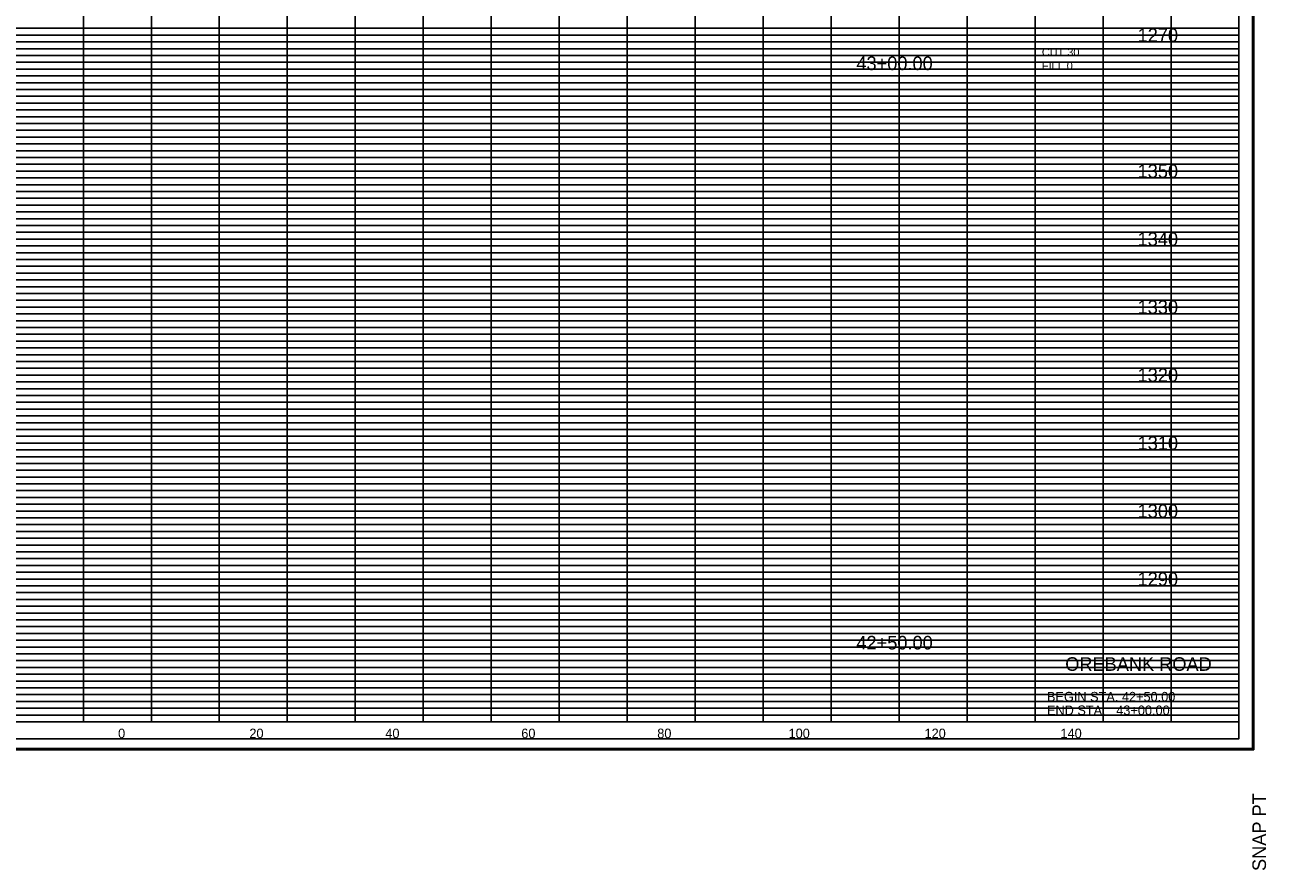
# Model space of a CAD drawing. Extents: x 980 to 1324, y 978 to 2847.
# Drawn here: x 1141.4 to 1324, y 978.2 to 1102.5 of the extents above; entities that cross this region are included whole.
import ezdxf

# ---------------------------------------------------------------- set-up
doc = ezdxf.new("R2010")
doc.units = 0
for name, color, linetype in [('DESIGN - SHEET - Corner Text', 7, 'Continuous'), ('DESIGN - SHEET - Light Grid', 7, 'Continuous'), ('DESIGN - SHEET - Linework', 7, 'Continuous'), ('DESIGN - SHEET - Plot Shape', 7, 'Continuous'), ('DESIGN - TYPICAL - Text', 7, 'Continuous')]:
    doc.layers.add(name, color=color, linetype=linetype)

# ---------------------------------------------------------------- blocks, each defined once
blk = doc.blocks.new('XSTSHT')
at = {"layer": 'DESIGN - SHEET - Light Grid'}
for p, q in [((8, 10.2), (16, 10.2)), ((8, 10.1), (16, 10.1)), ((16, 10.2), (24, 10.2)), ((16, 10.1), (24, 10.1)), ((24, 10.2), (32, 10.2)), ((24, 10.1), (32, 10.1)), ((8, 9.9), (16, 9.9)), ((16, 9.9), (24, 9.9)), ((24, 9.9), (32, 9.9)), ((8, 9.8), (16, 9.8)), ((8, 9.7), (16, 9.7)), ((16, 9.8), (24, 9.8)), ((16, 9.7), (24, 9.7)), ((24, 9.8), (32, 9.8)), ((24, 9.7), (32, 9.7)), ((8, 9.6), (16, 9.6)), ((8, 9.5), (16, 9.5)), ((16, 9.6), (24, 9.6)), ((16, 9.5), (24, 9.5)), ((24, 9.6), (32, 9.6)), ((24, 9.5), (32, 9.5)), ((8, 9.4), (16, 9.4)), ((16, 9.4), (24, 9.4)), ((24, 9.4), (32, 9.4)), ((8, 9.3), (16, 9.3)), ((8, 9.2), (16, 9.2)), ((16, 9.3), (24, 9.3)), ((16, 9.2), (24, 9.2)), ((24, 9.3), (32, 9.3)), ((24, 9.2), (32, 9.2)), ((8, 9.1), (16, 9.1)), ((16, 9.1), (24, 9.1)), ((24, 9.1), (32, 9.1)), ((8, 8.9), (16, 8.9)), ((8, 8.8), (16, 8.8)), ((16, 8.9), (24, 8.9)), ((16, 8.8), (24, 8.8)), ((24, 8.9), (32, 8.9)), ((24, 8.8), (32, 8.8)), ((8, 8.7), (16, 8.7)), ((8, 8.6), (16, 8.6)), ((16, 8.7), (24, 8.7)), ((16, 8.6), (24, 8.6)), ((24, 8.7), (32, 8.7)), ((24, 8.6), (32, 8.6)), ((8, 8.5), (16, 8.5)), ((16, 8.5), (24, 8.5)), ((24, 8.5), (32, 8.5)), ((8, 8.4), (16, 8.4)), ((8, 8.3), (16, 8.3)), ((16, 8.4), (24, 8.4)), ((16, 8.3), (24, 8.3)), ((24, 8.4), (32, 8.4)), ((24, 8.3), (32, 8.3)), ((8, 8.2), (16, 8.2)), ((8, 8.1), (16, 8.1)), ((16, 8.2), (24, 8.2)), ((16, 8.1), (24, 8.1)), ((24, 8.2), (32, 8.2)), ((24, 8.1), (32, 8.1)), ((8, 7.9), (16, 7.9)), ((16, 7.9), (24, 7.9)), ((24, 7.9), (32, 7.9)), ((8, 7.8), (16, 7.8)), ((8, 7.7), (16, 7.7)), ((16, 7.8), (24, 7.8)), ((16, 7.7), (24, 7.7)), ((24, 7.8), (32, 7.8)), ((24, 7.7), (32, 7.7)), ((8, 7.6), (16, 7.6)), ((8, 7.5), (16, 7.5)), ((16, 7.6), (24, 7.6)), ((16, 7.5), (24, 7.5)), ((24, 7.6), (32, 7.6)), ((24, 7.5), (32, 7.5)), ((8, 7.4), (16, 7.4)), ((16, 7.4), (24, 7.4)), ((24, 7.4), (32, 7.4)), ((8, 7.3), (16, 7.3)), ((8, 7.2), (16, 7.2)), ((16, 7.3), (24, 7.3)), ((16, 7.2), (24, 7.2)), ((24, 7.3), (32, 7.3)), ((24, 7.2), (32, 7.2)), ((8, 7.1), (16, 7.1)), ((16, 7.1), (24, 7.1)), ((24, 7.1), (32, 7.1)), ((8, 6.9), (16, 6.9)), ((8, 6.8), (16, 6.8)), ((16, 6.9), (24, 6.9)), ((16, 6.8), (24, 6.8)), ((24, 6.9), (32, 6.9)), ((24, 6.8), (32, 6.8)), ((8, 6.7), (16, 6.7)), ((8, 6.6), (16, 6.6)), ((16, 6.7), (24, 6.7)), ((16, 6.6), (24, 6.6)), ((24, 6.7), (32, 6.7)), ((24, 6.6), (32, 6.6)), ((8, 6.5), (16, 6.5)), ((8, 6.4), (16, 6.4)), ((16, 6.5), (24, 6.5)), ((16, 6.4), (24, 6.4)), ((24, 6.5), (32, 6.5)), ((24, 6.4), (32, 6.4)), ((8, 6.3), (16, 6.3)), ((16, 6.3), (24, 6.3)), ((24, 6.3), (32, 6.3)), ((8, 6.2), (16, 6.2)), ((8, 6.1), (16, 6.1)), ((16, 6.2), (24, 6.2)), ((16, 6.1), (24, 6.1)), ((24, 6.2), (32, 6.2)), ((24, 6.1), (32, 6.1)), ((8, 5.9), (16, 5.9)), ((16, 5.9), (24, 5.9)), ((24, 5.9), (32, 5.9)), ((8, 5.8), (16, 5.8)), ((8, 5.7), (16, 5.7)), ((16, 5.8), (24, 5.8)), ((16, 5.7), (24, 5.7)), ((24, 5.8), (32, 5.8)), ((24, 5.7), (32, 5.7)), ((8, 5.6), (16, 5.6)), ((8, 5.5), (16, 5.5)), ((16, 5.6), (24, 5.6)), ((16, 5.5), (24, 5.5)), ((24, 5.6), (32, 5.6)), ((24, 5.5), (32, 5.5)), ((8, 5.4), (16, 5.4)), ((8, 5.3), (16, 5.3)), ((16, 5.4), (24, 5.4)), ((16, 5.3), (24, 5.3)), ((24, 5.4), (32, 5.4)), ((24, 5.3), (32, 5.3)), ((8, 5.2), (16, 5.2)), ((16, 5.2), (24, 5.2)), ((24, 5.2), (32, 5.2)), ((8, 5.1), (16, 5.1)), ((16, 5.1), (24, 5.1)), ((24, 5.1), (32, 5.1)), ((8, 4.9), (16, 4.9)), ((8, 4.8), (16, 4.8)), ((16, 4.9), (24, 4.9)), ((16, 4.8), (24, 4.8)), ((24, 4.9), (32, 4.9)), ((24, 4.8), (32, 4.8)), ((8, 4.7), (16, 4.7)), ((8, 4.6), (16, 4.6)), ((16, 4.7), (24, 4.7)), ((16, 4.6), (24, 4.6)), ((24, 4.7), (32, 4.7)), ((24, 4.6), (32, 4.6)), ((8, 4.5), (16, 4.5)), ((8, 4.4), (16, 4.4)), ((16, 4.5), (24, 4.5)), ((16, 4.4), (24, 4.4)), ((24, 4.5), (32, 4.5)), ((24, 4.4), (32, 4.4)), ((8, 4.3), (16, 4.3)), ((16, 4.3), (24, 4.3)), ((24, 4.3), (32, 4.3)), ((8, 4.2), (16, 4.2)), ((8, 4.1), (16, 4.1)), ((16, 4.2), (24, 4.2)), ((16, 4.1), (24, 4.1)), ((24, 4.2), (32, 4.2)), ((24, 4.1), (32, 4.1)), ((8, 3.9), (16, 3.9)), ((16, 3.9), (24, 3.9)), ((24, 3.9), (32, 3.9)), ((8, 3.8), (16, 3.8)), ((8, 3.7), (16, 3.7)), ((16, 3.8), (24, 3.8)), ((16, 3.7), (24, 3.7)), ((24, 3.8), (32, 3.8)), ((24, 3.7), (32, 3.7)), ((8, 3.6), (16, 3.6)), ((8, 3.5), (16, 3.5)), ((16, 3.6), (24, 3.6)), ((16, 3.5), (24, 3.5)), ((24, 3.6), (32, 3.6)), ((24, 3.5), (32, 3.5)), ((8, 3.4), (16, 3.4)), ((8, 3.3), (16, 3.3)), ((16, 3.4), (24, 3.4)), ((16, 3.3), (24, 3.3)), ((24, 3.4), (32, 3.4)), ((24, 3.3), (32, 3.3)), ((8, 3.2), (16, 3.2)), ((16, 3.2), (24, 3.2)), ((24, 3.2), (32, 3.2)), ((8, 3.1), (16, 3.1)), ((16, 3.1), (24, 3.1)), ((24, 3.1), (32, 3.1)), ((8, 2.9), (16, 2.9)), ((8, 2.8), (16, 2.8)), ((16, 2.9), (24, 2.9)), ((16, 2.8), (24, 2.8)), ((24, 2.9), (32, 2.9)), ((24, 2.8), (32, 2.8)), ((8, 2.7), (16, 2.7)), ((8, 2.6), (16, 2.6)), ((16, 2.7), (24, 2.7)), ((16, 2.6), (24, 2.6)), ((24, 2.7), (32, 2.7)), ((24, 2.6), (32, 2.6)), ((8, 2.5), (16, 2.5)), ((8, 2.4), (16, 2.4)), ((16, 2.5), (24, 2.5)), ((16, 2.4), (24, 2.4)), ((24, 2.5), (32, 2.5)), ((24, 2.4), (32, 2.4)), ((8, 2.3), (16, 2.3)), ((8, 2.2), (16, 2.2)), ((16, 2.3), (24, 2.3)), ((16, 2.2), (24, 2.2)), ((24, 2.3), (32, 2.3)), ((24, 2.2), (32, 2.2)), ((8, 2.1), (16, 2.1)), ((16, 2.1), (24, 2.1)), ((24, 2.1), (32, 2.1)), ((8, 1.9), (16, 1.9)), ((16, 1.9), (24, 1.9)), ((24, 1.9), (32, 1.9)), ((8, 1.8), (16, 1.8)), ((8, 1.7), (16, 1.7)), ((16, 1.8), (24, 1.8)), ((16, 1.7), (24, 1.7)), ((24, 1.8), (32, 1.8)), ((24, 1.7), (32, 1.7)), ((8, 1.6), (16, 1.6)), ((8, 1.5), (16, 1.5)), ((16, 1.6), (24, 1.6)), ((16, 1.5), (24, 1.5)), ((24, 1.6), (32, 1.6)), ((24, 1.5), (32, 1.5)), ((8, 1.4), (16, 1.4)), ((8, 1.3), (16, 1.3)), ((16, 1.4), (24, 1.4)), ((16, 1.3), (24, 1.3)), ((24, 1.4), (32, 1.4)), ((24, 1.3), (32, 1.3)), ((8, 1.2), (16, 1.2)), ((8, 1.1), (16, 1.1)), ((16, 1.2), (24, 1.2)), ((16, 1.1), (24, 1.1)), ((24, 1.2), (32, 1.2)), ((24, 1.1), (32, 1.1)), ((8, 0.9), (16, 0.9)), ((8, 0.8), (16, 0.8)), ((16, 0.9), (24, 0.9)), ((16, 0.8), (24, 0.8)), ((24, 0.9), (32, 0.9)), ((24, 0.8), (32, 0.8)), ((8, 0.7), (16, 0.7)), ((8, 0.6), (16, 0.6)), ((16, 0.7), (24, 0.7)), ((16, 0.6), (24, 0.6)), ((24, 0.7), (32, 0.7)), ((24, 0.6), (32, 0.6)), ((8, 0.5), (16, 0.5)), ((8, 0.4), (16, 0.4)), ((16, 0.5), (24, 0.5)), ((16, 0.4), (24, 0.4)), ((24, 0.5), (32, 0.5)), ((24, 0.4), (32, 0.4)), ((8, 0.3), (16, 0.3)), ((8, 0.2), (16, 0.2)), ((16, 0.3), (24, 0.3)), ((16, 0.2), (24, 0.2)), ((24, 0.3), (32, 0.3)), ((24, 0.2), (32, 0.2)), ((8, 0.1), (16, 0.1)), ((16, 0.1), (24, 0.1)), ((24, 0.1), (32, 0.1))]:
    blk.add_line(p, q, dxfattribs=at)
at = {"layer": 'DESIGN - SHEET - Linework'}
for p, q in [((32.217, 21.414), (32.217, -0.414)), ((15, 0), (15, 21)), ((16, 0), (16, 21)), ((17, 0), (17, 21)), ((18, 0), (18, 21)), ((19, 0), (19, 21)), ((20, 0), (20, 21)), ((21, 0), (21, 21)), ((22, 0), (22, 21)), ((23, 0), (23, 21)), ((24, 0), (24, 21)), ((25, 0), (25, 21)), ((26, 0), (26, 21)), ((27, 0), (27, 21)), ((28, 0), (28, 20)), ((29, 0), (29, 20)), ((30, 0), (30, 20)), ((31, 0), (31, 20)), ((0, 10), (32, 10)), ((0, 9), (32, 9)), ((0, 8), (32, 8)), ((0, 7), (32, 7)), ((0, 6), (32, 6)), ((0, 5), (32, 5)), ((0, 4), (32, 4)), ((0, 3), (32, 3)), ((0, 2), (32, 2)), ((0, 1), (32, 1)), ((-1.823, -0.414), (32.217, -0.414))]:
    blk.add_line(p, q, dxfattribs=at)
blk.add_lwpolyline([(0, 21), (0, 0), (32, 0), (32, 21), (0, 21)], dxfattribs=at)
at = {"layer": 'DESIGN - SHEET - Plot Shape'}
for points in [[(-1.803, 21.394), (32.197, 21.394), (32.197, -0.394), (-1.803, -0.394)], [(-0.85, 21), (32, 21), (32, -0.25), (-0.85, -0.25)]]:
    blk.add_lwpolyline(points, close=True, dxfattribs=at)
at = {"layer": 'DESIGN - SHEET - Corner Text'}
blk.add_text('SNAP PT  ', height=0.2, rotation=90, dxfattribs=at).set_placement((32.397, -2.194))

msp = doc.modelspace()

# ---------------------------------------------------------------- linework, layer by layer
at = {"layer": 'DESIGN - SHEET - Plot Shape'}
msp.add_lwpolyline([(991.5, 997.5), (1320, 997.5), (1320, 1210), (991.5, 1210)], close=True, dxfattribs=at)

# ---------------------------------------------------------------- block references
at = {"layer": 'DESIGN - SHEET - Plot Shape', "xscale": 10, "yscale": 10}
msp.add_blockref('XSTSHT', (1000, 1000), dxfattribs=at)

# ---------------------------------------------------------------- texts
at = {"layer": 'DESIGN - SHEET - Corner Text'}
for s, height, p in [('OREBANK ROAD', 2, (1294.44, 1007.5)), ('BEGIN STA. 42+50.00', 1.4, (1291.75, 1003)), ('END STA.   43+00.00', 1.4, (1291.75, 1001))]:
    msp.add_text(s, height=height, dxfattribs=at).set_placement(p)
at = {"layer": 'DESIGN - TYPICAL - Text'}
for s, height, p in [('     1270     ', 2, (1301.37, 1100)), ('     43+00.00     ', 2, (1260, 1095.86)), ('CUT 30', 1.2, (1291, 1097.89)), ('FILL 0', 1.2, (1291, 1095.89)), ('     1350     ', 2, (1301.37, 1080)), ('     1340     ', 2, (1301.37, 1070)), ('     1330     ', 2, (1301.37, 1060)), ('     1320     ', 2, (1301.37, 1050)), ('     1310     ', 2, (1301.37, 1040)), ('     1300     ', 2, (1301.37, 1030)), ('     1290     ', 2, (1301.37, 1020)), ('     42+50.00     ', 2, (1260, 1010.64)), ('     0     ', 1.4, (1152.51, 997.6)), ('     0     ', 1.4, (1152.51, 997.6)), ('     20     ', 1.4, (1171.82, 997.6)), ('     40     ', 1.4, (1191.82, 997.6)), ('     60     ', 1.4, (1211.82, 997.6)), ('     80     ', 1.4, (1231.82, 997.6)), ('     100     ', 1.4, (1251.14, 997.6)), ('     120     ', 1.4, (1271.14, 997.6)), ('     140     ', 1.4, (1291.14, 997.6))]:
    msp.add_text(s, height=height, dxfattribs=at).set_placement(p)

doc.saveas('drawing.dxf')
